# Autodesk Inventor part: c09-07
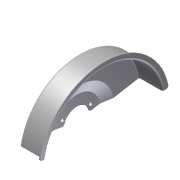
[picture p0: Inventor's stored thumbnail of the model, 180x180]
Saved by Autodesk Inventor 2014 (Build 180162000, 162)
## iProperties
Created: 2010-12
Part Number: c09-07
Material: Steel
Document SubType Name: Sheet Metal
Designer: Thom Tremblay
Density: 7.85 g/cm^3
Sheet Metal Rule: 16ga Steel
Sheet Metal Width: 0.000 mm
Sheet Metal Length: 0.000 mm
Sheet Metal Area: 0.000 mm^2
Appearance: Steel
Author: Thom Tremblay
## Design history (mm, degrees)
sketch "Sketch1"
  geometry: L1 (0, 0)-(52.833, 0); L2 (0, 18)-(0, 32.5); L3 (0, 32.5)-(5, 46.237); L4 (5, 46.237)-(5, 82.5); L5 (5, 82.5)-(38, 82.5); L6 (38, 82.5)-(38, 90.5)
  constraints: 12 end point, 2 parallel, 2 perpendicular, 1 horizontal, 1 point on line
  dimensions: "d0" = 165 diameter of L5 L1; "d1" = 33 distance of L4.end L5.end; "d3" = 36 diameter of L2.start L1; "d4" = 65 diameter of L2.end L1; "d6" = 38 distance between parallel lines of L6 L2 (derived); "d23" = 5 horizontal distance of L2.end L3.end; "d24" = 20 deg angle of L2 L3; "d25" = 8 distance of L5.end L6.end
feature "Contour Roll1" sketch "Sketch1" dims "d9" = 160 deg, "d10" = 175.23857, "d11" = 62.75269, "Thickness" = 1.524 (derived)
sketch "Sketch2"
  geometry: L1 (0, 0)-(-19.486, 11.25); L2 (19.486, 11.25)-(0, 0); L3 (0, 0)-(0, 22.5); A1 r 22.5 centre (0, 0) between (19.486, 11.25) and (-19.486, 11.25)
  constraints: 6 end point, 3 point on circle, 1 centre point, 1 vertical
  dimensions: "d12" = 22.5 radius of A1; "d13" = 120 deg angle of L1 L2; "d14" = 60 deg angle of L1 L3 (= 0.5 x d13)
hole "Hole1" sketch "Sketch2" at (-19.486, 11.25), (19.486, 11.25) diameter "d15" = 4.4958; stored, may be unused: countersink angle "d19" = 82 deg, drill point angle "d21" = 118 deg; dims "d16" = 19.05, "d17" = 8.4328, "d18" = 6.35, "d20" = 1.524 (= Thickness)
feature "Corner Round1" dims "d22" = 2.54
body "Solid1"
other parameters: "BendRadius" = 1.524 (= Thickness), "BendReliefWidth" = 1.524 (= Thickness), "BendReliefDepth" = 0.762 (= 0.5 x Thickness), "CornerReliefSize" = 6.096 (= 4 x Thickness), "SeamGap" = 0.00508, "MinimumRemnant" = 3.048 (= 2 x Thickness), "TransitionRadius" = 1.524 (= BendRadius), "JacobiRadiusSize" = 1.524 (= BendRadius), "GapSize" = 1.524 (= Thickness), "d8" = 1.524 (= BendRadius)
